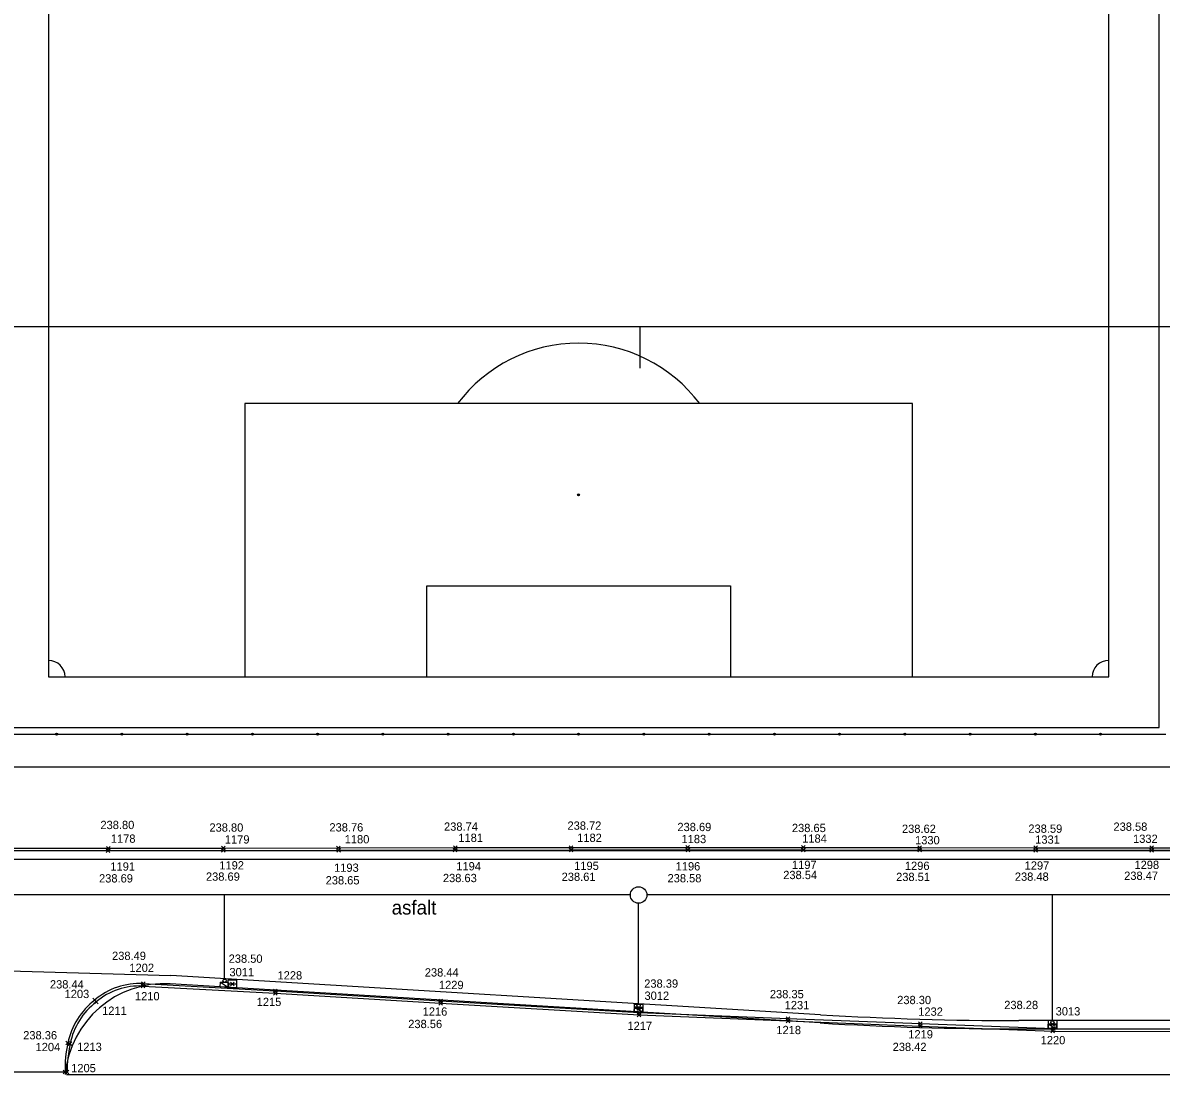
# Model space of a CAD drawing. Extents: x -264205 to -263615, y -1242401 to -1242031.
# Drawn here: x -264041.1 to -263972.3, y -1242315 to -1242251.5 of the extents above; entities that cross this region are included whole.
import ezdxf

# ---------------------------------------------------------------- set-up
doc = ezdxf.new("R2010")
doc.units = 0
for name, color, linetype in [('BODY_SYMBOL A CISLO_2-1', 7, 'Continuous'), ('BODY_VYSKA_2-1', 7, 'Continuous'), ('KOORDINACNA_SITUACIA_DSP', 7, 'Continuous'), ('POPIS', 7, 'Continuous'), ('PROJEKT_DRS_TDZ_VODOROVNE', 7, 'Continuous'), ('RAM_NA_TLAC_1-250_SITUACIA_2-1', 7, 'Continuous'), ('SO_20-1_OBRUBNIKY_DOLNA_HRANA', 7, 'Continuous'), ('SO_20-1_OBRUBNIKY_DOLNA_HRANA_POMOCNE', 7, 'Continuous'), ('SO_20-1_OBRUBNIKY_HORNA_HRANA', 7, 'Continuous'), ('SO_20-1_UV', 7, 'Continuous')]:
    doc.layers.add(name, color=color, linetype=linetype)

msp = doc.modelspace()

# ---------------------------------------------------------------- linework, layer by layer
at = {"layer": 'BODY_SYMBOL A CISLO_2-1'}
for p, q in [((-264022.129, -1242301.41), (-264021.908, -1242301.19)), ((-264021.908, -1242301.41), (-264022.129, -1242301.19)), ((-264015.065, -1242301.396), (-264014.844, -1242301.174)), ((-264014.844, -1242301.396), (-264015.065, -1242301.174)), ((-264008.085, -1242301.39), (-264007.864, -1242301.17)), ((-264007.864, -1242301.39), (-264008.085, -1242301.17)), ((-264001.052, -1242301.387), (-264000.831, -1242301.167)), ((-264000.831, -1242301.387), (-264001.052, -1242301.167)), ((-263994.06, -1242301.387), (-263993.839, -1242301.166)), ((-263993.839, -1242301.387), (-263994.06, -1242301.166)), ((-263987.034, -1242301.397), (-263986.812, -1242301.177)), ((-263986.812, -1242301.397), (-263987.034, -1242301.177)), ((-263980.034, -1242301.404), (-263979.812, -1242301.183)), ((-263979.812, -1242301.404), (-263980.034, -1242301.183)), ((-263973.03, -1242301.406), (-263972.809, -1242301.184)), ((-263972.809, -1242301.406), (-263973.03, -1242301.184)), ((-264036.03, -1242301.579), (-264035.809, -1242301.359)), ((-264035.809, -1242301.579), (-264036.03, -1242301.359)), ((-264036.028, -1242301.431), (-264035.807, -1242301.21)), ((-264035.807, -1242301.431), (-264036.028, -1242301.21)), ((-264029.083, -1242301.566), (-264028.861, -1242301.346)), ((-264028.861, -1242301.566), (-264029.083, -1242301.346)), ((-264029.078, -1242301.421), (-264028.856, -1242301.2)), ((-264028.856, -1242301.421), (-264029.078, -1242301.2)), ((-264022.114, -1242301.552), (-264021.893, -1242301.332)), ((-264021.893, -1242301.552), (-264022.114, -1242301.332)), ((-264015.084, -1242301.549), (-264014.863, -1242301.328)), ((-264014.863, -1242301.549), (-264015.084, -1242301.328)), ((-264008.079, -1242301.539), (-264007.858, -1242301.319)), ((-264007.858, -1242301.539), (-264008.079, -1242301.319)), ((-264001.019, -1242301.536), (-264000.799, -1242301.316)), ((-264000.799, -1242301.536), (-264001.019, -1242301.316)), ((-263994.062, -1242301.535), (-263993.841, -1242301.315)), ((-263993.841, -1242301.535), (-263994.062, -1242301.315)), ((-263987.031, -1242301.548), (-263986.81, -1242301.326)), ((-263986.81, -1242301.548), (-263987.031, -1242301.326)), ((-263980.035, -1242301.552), (-263979.813, -1242301.33)), ((-263979.813, -1242301.552), (-263980.035, -1242301.33)), ((-263973.03, -1242301.556), (-263972.808, -1242301.335)), ((-263972.808, -1242301.556), (-263973.03, -1242301.335)), ((-264033.916, -1242309.61), (-264033.694, -1242309.389)), ((-264033.694, -1242309.61), (-264033.916, -1242309.389)), ((-264028.527, -1242309.627), (-264028.306, -1242309.406)), ((-264028.306, -1242309.627), (-264028.527, -1242309.406)), ((-264033.93, -1242309.754), (-264033.709, -1242309.532)), ((-264033.709, -1242309.754), (-264033.93, -1242309.532)), ((-264025.943, -1242310.193), (-264025.722, -1242309.971)), ((-264025.722, -1242310.193), (-264025.943, -1242309.971)), ((-264025.94, -1242310.045), (-264025.719, -1242309.823)), ((-264025.719, -1242310.045), (-264025.94, -1242309.823)), ((-264036.84, -1242310.6), (-264036.619, -1242310.38)), ((-264036.619, -1242310.6), (-264036.84, -1242310.38)), ((-264036.747, -1242310.715), (-264036.526, -1242310.495)), ((-264036.526, -1242310.715), (-264036.747, -1242310.495)), ((-264015.965, -1242310.798), (-264015.743, -1242310.576)), ((-264015.743, -1242310.798), (-264015.965, -1242310.576)), ((-264015.959, -1242310.65), (-264015.737, -1242310.428)), ((-264015.737, -1242310.65), (-264015.959, -1242310.428)), ((-264004.012, -1242311.099), (-264003.791, -1242310.877)), ((-264003.791, -1242311.099), (-264004.012, -1242310.877)), ((-264003.982, -1242311.501), (-264003.761, -1242311.279)), ((-264003.761, -1242311.501), (-264003.982, -1242311.279)), ((-264003.974, -1242311.353), (-264003.753, -1242311.133)), ((-264003.753, -1242311.353), (-264003.974, -1242311.133)), ((-263994.985, -1242311.717), (-263994.764, -1242311.495)), ((-263994.764, -1242311.717), (-263994.985, -1242311.495)), ((-263994.992, -1242311.863), (-263994.77, -1242311.643)), ((-263994.77, -1242311.863), (-263994.992, -1242311.643)), ((-263986.997, -1242312.167), (-263986.775, -1242311.945)), ((-263986.775, -1242312.167), (-263986.997, -1242311.945)), ((-263986.992, -1242312.018), (-263986.771, -1242311.796)), ((-263986.771, -1242312.018), (-263986.992, -1242311.796)), ((-263979.007, -1242312.072), (-263978.785, -1242311.85)), ((-263978.785, -1242312.072), (-263979.007, -1242311.85)), ((-263978.967, -1242312.326), (-263978.746, -1242312.105)), ((-263978.746, -1242312.326), (-263978.967, -1242312.105)), ((-263979.007, -1242312.47), (-263978.785, -1242312.248)), ((-263978.785, -1242312.47), (-263979.007, -1242312.248)), ((-264038.469, -1242313.201), (-264038.247, -1242312.98)), ((-264038.247, -1242313.201), (-264038.469, -1242312.98)), ((-264038.326, -1242313.235), (-264038.105, -1242313.015)), ((-264038.105, -1242313.235), (-264038.326, -1242313.015)), ((-264038.632, -1242314.934), (-264038.41, -1242314.714)), ((-264038.41, -1242314.934), (-264038.632, -1242314.714)), ((-264038.512, -1242314.934), (-264038.291, -1242314.714)), ((-264038.291, -1242314.934), (-264038.512, -1242314.714))]:
    msp.add_line(p, q, dxfattribs=at)
at = {"layer": 'KOORDINACNA_SITUACIA_DSP'}
for p, q in [((-264039.518, -1242190.982), (-264039.518, -1242290.982)), ((-263975.518, -1242290.982), (-263975.518, -1242190.982)), ((-263987.358, -1242274.482), (-264027.678, -1242274.482)), ((-264027.678, -1242274.482), (-264027.678, -1242290.982)), ((-263987.358, -1242290.982), (-263987.358, -1242274.482)), ((-264016.678, -1242290.982), (-264016.678, -1242285.482)), ((-264016.678, -1242285.482), (-263998.358, -1242285.482)), ((-263998.358, -1242285.482), (-263998.358, -1242290.982)), ((-264039.518, -1242290.982), (-263975.518, -1242290.982)), ((-264045.118, -1242294.432), (-263972.068, -1242294.432)), ((-264038.969, -1242294.432), (-264039.089, -1242294.432)), ((-264039.029, -1242294.492), (-264039.029, -1242294.372)), ((-264035.03, -1242294.432), (-264035.15, -1242294.432)), ((-264035.09, -1242294.492), (-264035.09, -1242294.372)), ((-264031.091, -1242294.432), (-264031.211, -1242294.432)), ((-264031.151, -1242294.492), (-264031.151, -1242294.372)), ((-264027.152, -1242294.432), (-264027.272, -1242294.432)), ((-264027.212, -1242294.492), (-264027.212, -1242294.372)), ((-264023.213, -1242294.432), (-264023.333, -1242294.432)), ((-264023.273, -1242294.492), (-264023.273, -1242294.372)), ((-264019.274, -1242294.432), (-264019.394, -1242294.432)), ((-264019.334, -1242294.492), (-264019.334, -1242294.372)), ((-264015.336, -1242294.432), (-264015.456, -1242294.432)), ((-264015.396, -1242294.492), (-264015.396, -1242294.372)), ((-264011.397, -1242294.432), (-264011.517, -1242294.432)), ((-264011.457, -1242294.492), (-264011.457, -1242294.372)), ((-264007.458, -1242294.432), (-264007.578, -1242294.432)), ((-264007.518, -1242294.492), (-264007.518, -1242294.372)), ((-264003.519, -1242294.432), (-264003.639, -1242294.432)), ((-264003.579, -1242294.492), (-264003.579, -1242294.372)), ((-263999.58, -1242294.432), (-263999.7, -1242294.432)), ((-263999.64, -1242294.492), (-263999.64, -1242294.372)), ((-263995.641, -1242294.432), (-263995.761, -1242294.432)), ((-263995.701, -1242294.492), (-263995.701, -1242294.372)), ((-263991.702, -1242294.432), (-263991.822, -1242294.432)), ((-263991.762, -1242294.492), (-263991.762, -1242294.372)), ((-263987.763, -1242294.432), (-263987.883, -1242294.432)), ((-263987.823, -1242294.492), (-263987.823, -1242294.372)), ((-263983.824, -1242294.432), (-263983.944, -1242294.432)), ((-263983.884, -1242294.492), (-263983.884, -1242294.372)), ((-263979.886, -1242294.432), (-263980.006, -1242294.432)), ((-263979.946, -1242294.492), (-263979.946, -1242294.372)), ((-263975.947, -1242294.432), (-263976.067, -1242294.432)), ((-263976.007, -1242294.492), (-263976.007, -1242294.372)), ((-263971.068, -1242301.482), (-264112.961, -1242301.482)), ((-264004.396, -1242304.147), (-264044.527, -1242304.147)), ((-264028.895, -1242309.22), (-264028.89, -1242304.147)), ((-263954.413, -1242304.147), (-264003.396, -1242304.147)), ((-263978.913, -1242311.742), (-263978.913, -1242304.147)), ((-264003.896, -1242310.723), (-264003.896, -1242304.647)), ((-264029.162, -1242309.695), (-264029.144, -1242309.405)), ((-264029.144, -1242309.405), (-264028.645, -1242309.435)), ((-264029.144, -1242309.405), (-264028.663, -1242309.725)), ((-264029.144, -1242309.405), (-264028.663, -1242309.725)), ((-264028.645, -1242309.435), (-264029.144, -1242309.405)), ((-264028.645, -1242309.435), (-264028.663, -1242309.725)), ((-264028.663, -1242309.725), (-264028.645, -1242309.435)), ((-263992.94, -1242311.872), (-264032.171, -1242309.514)), ((-264032.171, -1242309.514), (-264032.171, -1242309.514)), ((-264028.663, -1242309.725), (-264029.162, -1242309.695)), ((-264004.163, -1242311.197), (-264004.146, -1242310.908)), ((-264003.664, -1242311.227), (-264004.163, -1242311.197)), ((-264004.146, -1242310.908), (-264003.646, -1242310.938)), ((-264004.146, -1242310.908), (-264003.664, -1242311.227)), ((-264004.146, -1242310.908), (-264003.664, -1242311.227)), ((-264003.646, -1242310.938), (-264004.146, -1242310.908)), ((-264003.646, -1242310.938), (-264003.664, -1242311.227)), ((-264003.664, -1242311.227), (-264003.646, -1242310.938)), ((-263979.163, -1242311.942), (-263978.663, -1242311.942)), ((-263979.163, -1242312.232), (-263979.163, -1242311.942)), ((-263979.163, -1242311.942), (-263978.663, -1242312.232)), ((-263979.163, -1242311.942), (-263978.663, -1242312.232)), ((-263978.663, -1242311.942), (-263979.163, -1242311.942)), ((-263978.663, -1242311.942), (-263978.663, -1242312.232)), ((-263978.663, -1242312.232), (-263978.663, -1242311.942)), ((-263980.94, -1242312.232), (-263857.327, -1242312.232)), ((-263978.663, -1242312.232), (-263979.163, -1242312.232)), ((-264038.443, -1242314.982), (-263836.403, -1242314.982))]:
    msp.add_line(p, q, dxfattribs=at)
msp.add_lwpolyline([(-264042.568, -1242294.032), (-263972.468, -1242294.032), (-263972.468, -1242187.932), (-264042.568, -1242187.932)], close=True, dxfattribs=at)
msp.add_lwpolyline([(-263965.143, -1242296.432), (-264120.018, -1242296.432), (-264120.282, -1242296.432)], dxfattribs=at)
for centre, radius in [((-264007.518, -1242279.982), 0.06), ((-264039.029, -1242294.432), 0.06), ((-264035.09, -1242294.432), 0.06), ((-264031.151, -1242294.432), 0.06), ((-264027.212, -1242294.432), 0.06), ((-264023.273, -1242294.432), 0.06), ((-264019.334, -1242294.432), 0.06), ((-264015.396, -1242294.432), 0.06), ((-264011.457, -1242294.432), 0.06), ((-264007.518, -1242294.432), 0.06), ((-264003.579, -1242294.432), 0.06), ((-263999.64, -1242294.432), 0.06), ((-263995.701, -1242294.432), 0.06), ((-263991.762, -1242294.432), 0.06), ((-263987.823, -1242294.432), 0.06), ((-263983.884, -1242294.432), 0.06), ((-263979.946, -1242294.432), 0.06), ((-263976.007, -1242294.432), 0.06), ((-264003.896, -1242304.147), 0.5), ((-264028.895, -1242309.32), 0.1), ((-264003.896, -1242310.823), 0.1), ((-263978.913, -1242311.842), 0.1)]:
    msp.add_circle(centre, radius, dxfattribs=at)
for centre, radius, start, end in [((-264007.518, -1242279.982), 9.15, 36.94821, 143.05179), ((-264007.518, -1242279.982), 0.0303, 90, 270), ((-264007.518, -1242279.982), 0.0303, 270, 90), ((-264039.518, -1242290.982), 1, 0, 90), ((-263975.518, -1242290.982), 1, 90, 180), ((-264032.531, -1242315.503), 6, 86.56019, 175.02052), ((-263980.94, -1242112.232), 200, 266.56019, 270)]:
    msp.add_arc(centre, radius, start, end, dxfattribs=at)
at = {"layer": 'PROJEKT_DRS_TDZ_VODOROVNE'}
for p, q in [((-264112.961, -1242301.982), (-263971.806, -1242301.982)), ((-264050.531, -1242308.482), (-264032.141, -1242309.015)), ((-263992.91, -1242311.373), (-264032.141, -1242309.015)), ((-263842.661, -1242311.732), (-263980.94, -1242311.732))]:
    msp.add_line(p, q, dxfattribs=at)
msp.add_arc((-263980.94, -1242112.232), 199.5, 266.56019, 270, dxfattribs=at)
at = {"layer": 'RAM_NA_TLAC_1-250_SITUACIA_2-1'}
msp.add_line((-264003.833, -1242269.835), (-264003.833, -1242272.335), dxfattribs=at)
msp.add_lwpolyline([(-264151.333, -1242269.835), (-263718.833, -1242269.835), (-263718.833, -1242344.085), (-264151.333, -1242344.085)], close=True, dxfattribs=at)
at = {"layer": 'SO_20-1_OBRUBNIKY_DOLNA_HRANA'}
for points in [[(-264084.992, -1242301.468), (-264078.002, -1242301.482), (-264070.986, -1242301.489), (-264064.021, -1242301.482), (-264056.978, -1242301.482), (-264049.977, -1242301.481), (-264042.921, -1242301.475), (-264035.92, -1242301.469), (-264028.972, -1242301.456), (-264022.003, -1242301.442), (-264014.974, -1242301.438), (-264007.969, -1242301.429), (-264000.909, -1242301.426), (-263993.952, -1242301.425)], [(-263993.952, -1242301.425), (-263986.921, -1242301.437), (-263979.924, -1242301.441), (-263972.919, -1242301.445), (-263970.912, -1242301.438)], [(-264033.805, -1242309.499), (-264025.829, -1242309.934), (-264015.848, -1242310.539), (-264003.863, -1242311.243), (-263994.874, -1242311.606), (-263986.882, -1242311.907), (-263978.856, -1242312.215), (-263970.892, -1242312.243), (-263962.891, -1242312.248), (-263954.893, -1242312.255), (-263953.892, -1242312.266), (-263946.9, -1242312.261), (-263936.904, -1242312.253), (-263927.909, -1242312.236)]]:
    msp.add_lwpolyline(points, dxfattribs=at)
for centre, major_axis, ratio, start_param, end_param in [((-264034.026, -1242313.661), (0.481, 4.14), 0.999833, 0.062646, 0.82187), ((-264034.01, -1242313.997), (-3.876, -2.174), 0.998598, 4.860749, 5.565783), ((-264031.337, -1242314.585), (-3.403, -6.376), 0.992668, 4.990922, 5.232731)]:
    msp.add_ellipse(centre, major_axis=major_axis, ratio=ratio, start_param=start_param, end_param=end_param, dxfattribs=at)
at = {"layer": 'SO_20-1_OBRUBNIKY_DOLNA_HRANA_POMOCNE'}
msp.add_line((-264044.462, -1242314.814), (-264038.521, -1242314.824), dxfattribs=at)
at = {"layer": 'SO_20-1_OBRUBNIKY_HORNA_HRANA'}
for points in [[(-264084.994, -1242301.327), (-264077.993, -1242301.335), (-264070.958, -1242301.339), (-264063.998, -1242301.345), (-264056.974, -1242301.334), (-264049.976, -1242301.332), (-264042.963, -1242301.324), (-264035.917, -1242301.32), (-264028.967, -1242301.31), (-264022.019, -1242301.3), (-264014.954, -1242301.285), (-264007.975, -1242301.28), (-264000.942, -1242301.277), (-263993.949, -1242301.276)], [(-263993.949, -1242301.276), (-263986.923, -1242301.287), (-263979.923, -1242301.293), (-263972.92, -1242301.295), (-263970.913, -1242301.29)], [(-264033.819, -1242309.643), (-264025.833, -1242310.082), (-264015.854, -1242310.687), (-264003.872, -1242311.39), (-263994.881, -1242311.753), (-263986.886, -1242312.056), (-263978.896, -1242312.359), (-263970.883, -1242312.387), (-263962.888, -1242312.396), (-263954.878, -1242312.403), (-263953.896, -1242312.41), (-263946.895, -1242312.406), (-263936.899, -1242312.396), (-263927.906, -1242312.382)]]:
    msp.add_lwpolyline(points, dxfattribs=at)
for centre, major_axis, ratio, start_param, end_param in [((-264034.033, -1242313.625), (-1.327, 3.76), 0.99987, 5.8902, 6.655533), ((-264034.073, -1242313.959), (-3.712, -2.023), 0.998497, 4.865889, 5.584759), ((-264033.999, -1242314.008), (-1.241, -6.235), 0.677566, 4.705598, 4.976492)]:
    msp.add_ellipse(centre, major_axis=major_axis, ratio=ratio, start_param=start_param, end_param=end_param, dxfattribs=at)
at = {"layer": 'SO_20-1_UV'}
for p, q in [((-264028.416, -1242309.516), (-264028.416, -1242309.516)), ((-264003.901, -1242310.988), (-264003.901, -1242310.988)), ((-263978.896, -1242311.961), (-263978.896, -1242311.961))]:
    msp.add_line(p, q, dxfattribs=at)
for points in [[(-264028.666, -1242309.516), (-264028.666, -1242309.266), (-264028.166, -1242309.266), (-264028.166, -1242309.766), (-264028.666, -1242309.766), (-264028.666, -1242309.516), (-264028.166, -1242309.516)], [(-264004.151, -1242310.988), (-264004.151, -1242310.738), (-264003.651, -1242310.738), (-264003.651, -1242311.238), (-264004.151, -1242311.238), (-264004.151, -1242310.988), (-264003.651, -1242310.988)], [(-263979.146, -1242311.961), (-263979.146, -1242311.711), (-263978.646, -1242311.711), (-263978.646, -1242312.211), (-263979.146, -1242312.211), (-263979.146, -1242311.961), (-263978.646, -1242311.961)]]:
    msp.add_lwpolyline(points, dxfattribs=at)

# ---------------------------------------------------------------- texts
at = {"layer": 'BODY_SYMBOL A CISLO_2-1'}
for s, p in [('1178', (-264035.757, -1242300.994)), ('1181', (-264014.779, -1242300.944)), ('1182', (-264007.605, -1242300.943)), ('1184', (-263994.02, -1242300.988)), ('1332', (-263974.048, -1242301.003)), ('1179', (-264028.874, -1242301.042)), ('1180', (-264021.639, -1242301.031)), ('1183', (-264001.305, -1242301.016)), ('1330', (-263987.208, -1242301.087)), ('1331', (-263979.955, -1242301.051)), ('1191', (-264035.786, -1242302.678)), ('1192', (-264029.208, -1242302.605)), ('1193', (-264022.281, -1242302.748)), ('1194', (-264014.902, -1242302.661)), ('1195', (-264007.787, -1242302.635)), ('1196', (-264001.661, -1242302.664)), ('1197', (-263994.639, -1242302.576)), ('1296', (-263987.822, -1242302.636)), ('1297', (-263980.593, -1242302.617)), ('1298', (-263973.962, -1242302.577)), ('1202', (-264034.638, -1242308.793)), ('3011', (-264028.598, -1242309.055)), ('1228', (-264025.695, -1242309.248)), ('1229', (-264015.951, -1242309.828)), ('1203', (-264038.549, -1242310.37)), ('1210', (-264034.302, -1242310.506)), ('3012', (-264003.541, -1242310.477)), ('1215', (-264026.953, -1242310.85)), ('1231', (-263995.08, -1242311.043)), ('1211', (-264036.285, -1242311.382)), ('1216', (-264016.933, -1242311.432)), ('1232', (-263987.016, -1242311.437)), ('3013', (-263978.721, -1242311.419)), ('1217', (-264004.571, -1242312.297)), ('1218', (-263995.58, -1242312.548)), ('1219', (-263987.616, -1242312.806)), ('1220', (-263979.626, -1242313.159)), ('1204', (-264040.301, -1242313.575)), ('1213', (-264037.794, -1242313.565)), ('1205', (-264038.151, -1242314.848))]:
    msp.add_text(s, height=0.5, dxfattribs=at).set_placement(p)
at = {"layer": 'BODY_VYSKA_2-1'}
for s, p in [('238.80', (-264036.386, -1242300.168)), ('238.80', (-264029.806, -1242300.323)), ('238.76', (-264022.562, -1242300.313)), ('238.74', (-264015.644, -1242300.267)), ('238.72', (-264008.191, -1242300.207)), ('238.69', (-264001.554, -1242300.29)), ('238.58', (-263975.231, -1242300.271)), ('238.65', (-263994.641, -1242300.349)), ('238.62', (-263987.997, -1242300.399)), ('238.59', (-263980.368, -1242300.392)), ('238.69', (-264036.47, -1242303.392)), ('238.69', (-264030.016, -1242303.286)), ('238.65', (-264022.791, -1242303.509)), ('238.63', (-264015.711, -1242303.371)), ('238.61', (-264008.543, -1242303.298)), ('238.58', (-264002.15, -1242303.384)), ('238.54', (-263995.166, -1242303.188)), ('238.51', (-263988.352, -1242303.304)), ('238.48', (-263981.184, -1242303.289)), ('238.47', (-263974.585, -1242303.234)), ('238.49', (-264035.684, -1242308.07)), ('238.50', (-264028.646, -1242308.24)), ('238.44', (-264016.805, -1242309.069)), ('238.44', (-264039.435, -1242309.791)), ('238.39', (-264003.558, -1242309.744)), ('238.35', (-263995.972, -1242310.381)), ('238.30', (-263988.286, -1242310.736)), ('238.28', (-263981.824, -1242311.036)), ('238.56', (-264017.804, -1242312.183)), ('238.36', (-264041.048, -1242312.864)), ('238.42', (-263988.561, -1242313.567))]:
    msp.add_text(s, height=0.5, dxfattribs=at).set_placement(p)
at = {"layer": 'POPIS'}
msp.add_text('asfalt', height=0.8438, dxfattribs=at).set_placement((-264018.805, -1242305.325))

doc.saveas('drawing.dxf')
